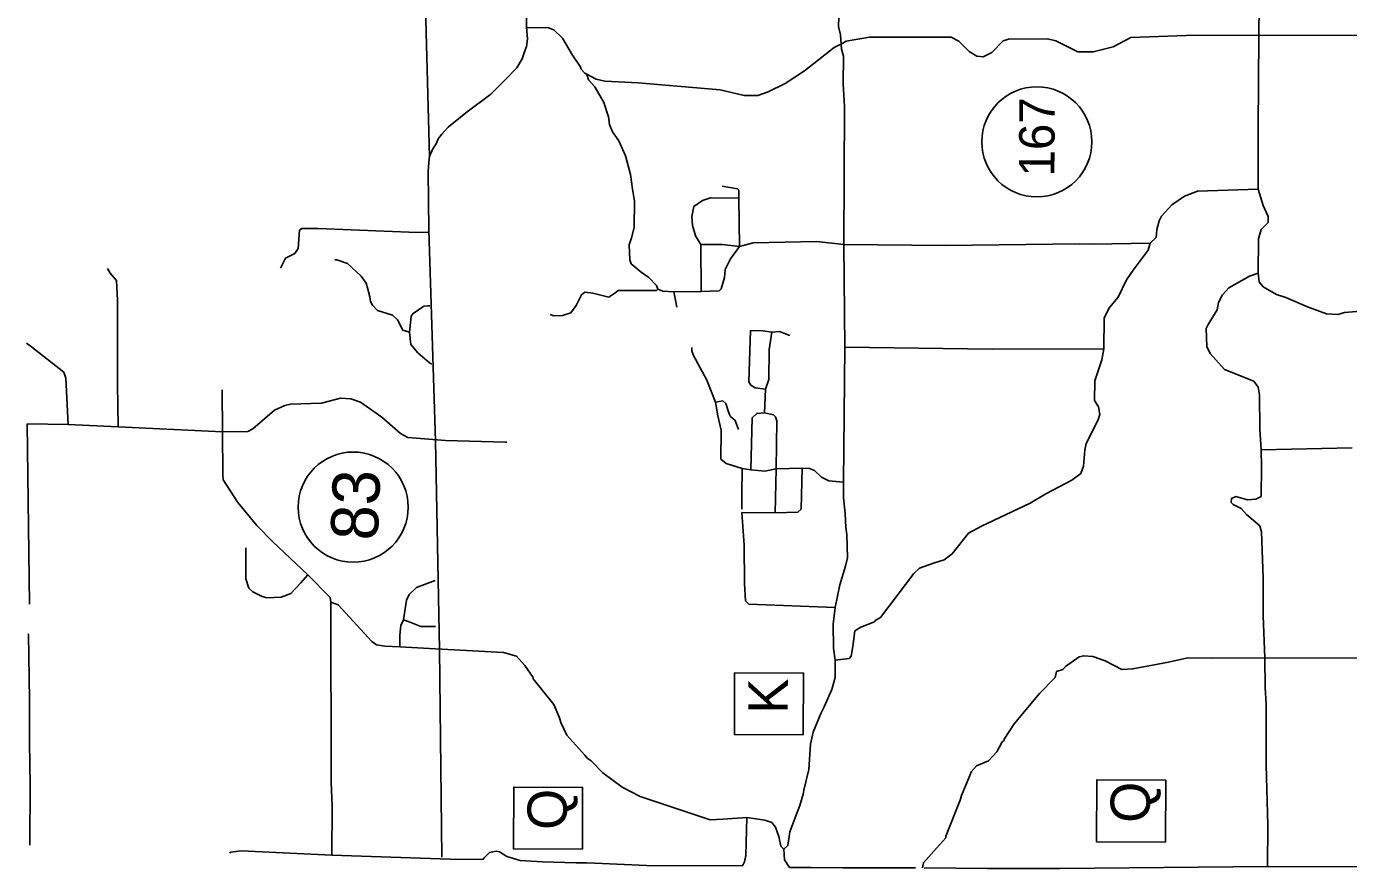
# Model space of a CAD drawing. Extents: x 299354 to 1325680, y 96128 to 228242.
# Drawn here: x 299575 to 333137, y 100282 to 121656 of the extents above; entities that cross this region are included whole.
import ezdxf

# ---------------------------------------------------------------- set-up
doc = ezdxf.new("R2010")
doc.units = 0
for name, color, linetype in [('Level 12', 7, 'Continuous'), ('Level 13', 7, 'Continuous'), ('Level 2', 7, 'Continuous'), ('Level 4', 7, 'Continuous')]:
    doc.layers.add(name, color=color, linetype=linetype)

msp = doc.modelspace()

# ---------------------------------------------------------------- linework, layer by layer
at = {"layer": 'Level 12'}
for p, q in [((325225, 118727), (325225, 118727)), ((307869, 109456), (307869, 109456))]:
    msp.add_line(p, q, dxfattribs=at)
for centre in [(325225, 118727), (307869, 109456)]:
    msp.add_circle(centre, 1398, dxfattribs=at)
at = {"layer": 'Level 13'}
for p, q in [((318402, 104496), (318402, 104496)), ((327597, 101775), (327597, 101775)), ((312794, 101594), (312794, 101594))]:
    msp.add_line(p, q, dxfattribs=at)
for points in [[(319296, 103674), (317546, 103681), (317553, 105251), (319303, 105244)], [(328491, 100953), (326741, 100960), (326747, 102530), (328497, 102523)], [(313688, 100773), (311938, 100780), (311944, 102350), (313694, 102343)]]:
    msp.add_lwpolyline(points, close=True, dxfattribs=at)
at = {"layer": 'Level 2'}
for points in [[(312239, 125880), (312267, 121630)], [(320301, 124724), (320314, 124232), (320273, 123458), (320250, 122774), (320213, 122408), (320190, 121658), (320238, 121441), (320268, 121083), (320316, 120899), (320310, 120199)], [(330885, 123820), (330862, 121406)], [(310120, 100570), (310060, 105839), (309959, 111142), (309790, 116486), (309773, 117983), (309788, 118200), (309803, 118351), (309892, 118552), (309974, 118678), (310023, 118804), (310122, 118922), (310188, 118998), (310279, 119099), (310725, 119462), (311363, 119936), (311710, 120281), (312024, 120610), (312155, 120837), (312220, 121013), (312268, 121147), (312291, 121331), (312266, 121649)], [(312267, 121630), (312825, 121625), (312967, 121574), (313181, 121355), (313436, 120928), (313650, 120617), (313650, 120584), (313749, 120467), (314039, 120314), (314256, 120270), (315106, 120229), (317189, 120044), (317797, 119905), (318139, 119902), (318406, 119999), (318834, 120212), (319329, 120533), (320076, 121118), (320303, 121232), (320386, 121281), (320979, 121384), (323048, 121382), (323247, 121281), (323503, 121020), (323702, 120901), (323860, 120883), (324078, 120998), (324373, 121287), (324507, 121336), (325491, 121344), (325707, 121292), (326264, 121012), (326655, 121008), (327165, 121137), (327610, 121374), (329011, 121428), (334049, 121433)], [(320310, 120199), (320338, 119624), (320322, 116124)], [(320322, 116124), (320348, 113515)], [(320316, 110090), (320348, 113515)], [(320104, 106909), (320226, 107483), (320363, 107956), (320415, 108172), (320404, 108764), (320373, 108940), (320359, 109298), (320313, 109698), (320316, 110090)], [(320104, 106909), (320050, 106484), (320061, 105876), (320108, 105567)], [(309956, 105860), (311686, 105768), (312019, 105673), (312225, 105438), (312439, 105128), (312439, 105095), (312959, 104448), (313106, 104105), (313138, 103988), (313293, 103670), (313747, 103158), (313813, 103082), (313913, 103015), (314210, 102712), (314699, 102349), (315155, 102112), (316935, 101520), (317252, 101534), (317861, 101579)], [(318804, 100770), (318905, 100869), (318950, 101211), (319104, 101618), (319207, 101883), (319293, 102174), (319310, 102274), (319432, 102798), (319479, 103439), (319549, 103747), (319737, 104220), (319822, 104386), (320018, 104826), (320104, 105134), (320108, 105567)], [(317861, 101579), (318319, 101508), (318494, 101448), (318593, 101330), (318674, 101096), (318722, 100854), (318804, 100770)], [(318804, 100770), (318819, 100503), (318942, 100311)], [(318942, 100311), (319484, 100306)], [(319484, 100306), (320309, 100298)], [(320309, 100298), (322144, 100298)], [(322361, 100296), (323971, 100282)], [(323971, 100282), (325805, 100282)], [(325805, 100282), (331077, 100334)], [(331077, 100334), (333462, 100329)]]:
    msp.add_lwpolyline(points, dxfattribs=at)
at = {"layer": 'Level 4'}
for points in [[(309594, 126238), (309803, 118351)], [(330862, 121406), (330841, 119087), (330843, 117528)], [(313798, 120433), (313847, 120299), (314004, 120123), (314234, 119729), (314347, 119361), (314379, 119169), (314452, 118985), (314617, 118750), (314780, 118374), (314909, 117898), (314964, 117522), (315011, 117222), (315005, 116555), (314936, 116289), (314876, 116115), (314889, 115731), (314930, 115631), (315178, 115420), (315377, 115285), (315567, 115083), (315600, 114991)], [(317233, 117602), (317625, 117531), (317658, 117498), (317656, 117298)], [(328103, 116153), (328255, 116302), (328274, 116502), (328326, 116726), (328393, 116842), (328655, 117131), (328973, 117345), (329300, 117476), (330843, 117528)], [(330843, 117528), (330973, 117111), (331095, 116834), (331094, 116684), (330917, 116503), (330848, 116262), (330840, 115395)], [(316694, 116123), (316563, 116341), (316482, 116608), (316467, 116833), (316520, 117083), (316738, 117239), (316939, 117304), (317656, 117298)], [(317656, 117298), (317678, 116072)], [(306022, 115520), (306149, 115777), (306384, 115891), (306469, 116024), (306506, 116482), (306565, 116531), (306982, 116528), (309491, 116422), (309767, 116436)], [(317678, 116072), (318021, 116161), (319631, 116196), (320322, 116124)], [(322916, 116100), (326302, 116136), (326644, 116133), (328103, 116153)], [(326928, 113472), (326935, 114264), (327071, 114521), (327290, 114785), (327503, 115225), (327672, 115474), (328052, 115979), (328103, 116153)], [(316694, 116123), (316700, 114931)], [(316694, 116123), (317236, 116118), (317678, 116072)], [(316700, 114931), (317159, 114944), (317209, 114993), (317295, 115284), (317314, 115484), (317450, 115758), (317678, 116072)], [(320322, 116124), (322916, 116100)], [(301635, 115509), (301701, 115392), (301857, 115207), (301886, 114699), (301883, 112574), (301907, 111490)], [(307400, 115732), (307450, 115732), (307724, 115638), (308072, 115318), (308195, 115142), (308244, 114991), (308292, 114791), (308308, 114674), (308357, 114582), (308489, 114447), (308863, 114327), (308996, 114209), (309127, 113950), (309301, 113898)], [(330840, 115395), (330623, 115314), (330095, 115018), (329935, 114845), (329833, 114646), (329798, 114463), (329577, 114090), (329526, 113990), (329539, 113532), (329621, 113356), (329992, 112953), (330732, 112654), (330847, 112503), (330878, 112295), (330887, 111436), (330916, 110911)], [(330840, 115395), (330872, 115178), (330971, 115044), (331311, 114849), (331544, 114780), (332092, 114542), (332574, 114363), (332866, 114343), (333033, 114392), (333642, 114445), (333850, 114409)], [(312866, 114341), (312966, 114307), (313183, 114321), (313392, 114386), (313527, 114577), (313663, 114842), (313747, 114908), (313956, 114889), (314363, 114786), (314514, 114884), (314598, 114950), (315566, 114958), (315600, 114991)], [(315600, 114991), (315733, 114940), (316008, 114921)], [(316008, 114921), (316700, 114931)], [(316008, 114921), (316039, 114754), (316083, 114532)], [(309301, 113898), (309338, 114306), (309389, 114372), (309666, 114553), (309766, 114569), (309816, 114569)], [(309301, 113898), (309332, 113581), (309513, 113371), (309803, 113119), (309869, 113085)], [(318337, 112450), (318070, 112486), (317962, 112553), (317913, 112637), (317958, 113937), (318267, 113934), (318500, 113898)], [(318337, 112450), (318422, 112699), (318429, 113457), (318500, 113898)], [(318500, 113898), (318692, 113913), (318958, 113811)], [(299575, 113616), (299699, 113527), (300527, 112878), (300575, 112727), (300631, 111552)], [(316464, 113508), (316469, 113425), (316502, 113325), (316846, 112680), (317066, 112120)], [(320108, 105567), (320459, 105614), (320509, 105672), (320553, 105921), (320607, 106312), (320758, 106411), (321101, 106541), (321118, 106574), (321252, 106657), (322105, 107774), (322248, 107906), (322599, 108036), (322875, 108117), (323077, 108273), (323490, 108795), (323817, 108975), (325057, 109556), (325451, 109794), (326113, 110138), (326340, 110311), (326408, 110493), (326445, 110901), (326480, 111068), (326769, 111657), (326821, 111806), (326789, 111998), (326691, 112166), (326695, 112657), (326875, 113197), (326928, 113472)], [(320348, 113515), (324092, 113464), (326928, 113472)], [(318314, 111850), (318337, 112450)], [(304546, 112429), (304549, 111366)], [(304549, 111366), (305191, 111377), (305325, 111443), (305872, 111913), (306132, 112035), (306282, 112067), (307066, 112093), (307551, 112222), (307809, 112203), (308059, 112118), (308597, 111738), (309069, 111325), (309260, 111224), (310210, 111148), (311736, 111101), (311769, 111101)], [(317066, 112120), (317250, 112151), (317332, 112084), (317413, 111825), (317446, 111758), (317570, 111657), (317652, 111423)], [(317066, 112120), (317129, 111777), (317209, 111410), (317203, 110677), (317335, 110559), (317743, 110438)], [(317967, 110403), (317996, 111719), (318114, 111835), (318314, 111850)], [(318314, 111850), (318539, 111798), (318589, 111747), (318621, 111647), (318610, 110431)], [(299597, 111569), (299655, 106994)], [(299597, 111569), (300631, 111552)], [(300631, 111552), (301907, 111490)], [(301907, 111490), (304549, 111366)], [(304549, 111366), (304556, 110283), (304571, 110149), (304941, 109571), (305420, 108992), (305824, 108580), (306717, 107738)], [(330916, 110911), (330928, 110486), (330921, 109727), (330787, 109654), (330570, 109639), (330279, 109725), (330162, 109676), (330161, 109576), (330211, 109526), (330410, 109424), (330550, 109272), (330881, 108978), (330930, 108827), (330969, 107660), (330969, 106694), (331009, 105627)], [(330916, 110911), (333226, 110957)], [(317733, 109405), (317736, 109772), (317743, 110438)], [(317743, 110438), (317967, 110403)], [(317967, 110403), (318317, 110367), (318610, 110431)], [(318583, 109314), (319158, 109326), (319243, 109408), (319269, 110441)], [(318583, 109314), (318610, 110431)], [(318610, 110431), (319269, 110441)], [(319269, 110441), (319452, 110440), (319577, 110388), (319759, 110212), (319941, 110127), (320316, 110090)], [(317732, 109322), (317791, 108488), (317799, 107521), (317828, 107079), (317911, 106995), (320104, 106909)], [(317732, 109322), (318583, 109314)], [(305147, 108419), (305140, 107636), (305221, 107402), (305321, 107309), (305561, 107190), (305678, 107156), (306037, 107169), (306288, 107267), (306532, 107523), (306717, 107738)], [(306717, 107738), (307287, 107158), (307303, 107041)], [(309150, 106599), (309222, 107090), (309290, 107240), (309475, 107413), (309952, 107592)], [(307303, 107041), (307311, 102466), (307339, 101874), (307327, 100624)], [(307303, 107041), (307486, 106973), (308345, 106048), (308461, 105964), (308669, 105929), (309052, 105909)], [(309052, 105909), (309055, 106209), (309082, 106450), (309150, 106599)], [(309150, 106599), (309333, 106531), (309583, 106429), (309958, 106425)], [(299607, 106228), (299631, 106227)], [(299631, 106227), (299649, 104552), (299656, 103485), (299671, 102402), (299657, 100910)], [(309052, 105909), (309956, 105860)], [(325726, 105283), (325885, 105331), (325953, 105414), (326297, 105653), (326414, 105685), (326647, 105666), (326955, 105555), (327378, 105334), (327662, 105348), (328564, 105524), (329057, 105628), (329683, 105622)], [(329683, 105622), (331009, 105627)], [(331009, 105627), (331018, 104876), (331048, 104451), (331050, 102909), (331086, 101384), (331077, 100334)], [(331009, 105627), (333394, 105622)], [(322322, 100298), (322346, 100430), (322607, 100719), (322910, 101058), (322911, 101108), (323278, 102021), (323312, 102138), (323568, 102744), (323694, 102893), (323996, 103015), (324206, 103246), (324342, 103495), (324393, 103536), (324393, 103570), (324647, 103951), (325288, 104728), (325692, 105133), (325726, 105283)], [(315314, 100360), (317750, 100355), (317801, 100454), (317835, 100612), (317861, 101579)], [(299648, 100911), (299657, 100910)], [(299657, 100878), (299657, 100910)], [(304739, 100672), (304751, 100697), (305026, 100728), (307327, 100624)], [(307327, 100624), (310329, 100522), (311163, 100514), (311196, 100556), (311331, 100688), (311498, 100720), (311581, 100702), (311772, 100584), (312105, 100489), (312672, 100451), (313530, 100426), (313789, 100424)], [(313789, 100424), (314006, 100422), (315314, 100360)]]:
    msp.add_lwpolyline(points, dxfattribs=at)

# ---------------------------------------------------------------- texts
at = {"layer": 'Level 12'}
for s, height, rotation, p in [('167', 900, 89.767, (325671, 117847)), ('83', 1200, 87.767, (308491, 108596))]:
    msp.add_text(s, height=height, rotation=rotation, dxfattribs=at).set_placement(p)
at = {"layer": 'Level 13'}
for s, p in [('K', (318901, 104210)), ('Q', (328095, 101442)), ('Q', (313293, 101262))]:
    msp.add_text(s, height=1000, rotation=89.767, dxfattribs=at).set_placement(p)

doc.saveas('drawing.dxf')
